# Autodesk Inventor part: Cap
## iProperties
Shininess: 77.0
Length Units: 11269
Angle Units: 11279
Time Units: 11290
Mass Units: 11283
Length Display Precision: 3
Angle Display Precision: 2
Created: 2002-02
Part Number: Cap
Document SubType Name: Modeling
Designer: ***
Density: 0.0
Volumn: 0.0
Area: 0.0
PropertySet Name: Model Information
Control State: 0
Master: False
Checked Out: False
Author: ***
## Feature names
1. Extrusion1
2. Extrusion2
3. Mirror1
4. Hole1
5. Rectangular Pattern1
6. Hole2
7. Rectangular Pattern2
